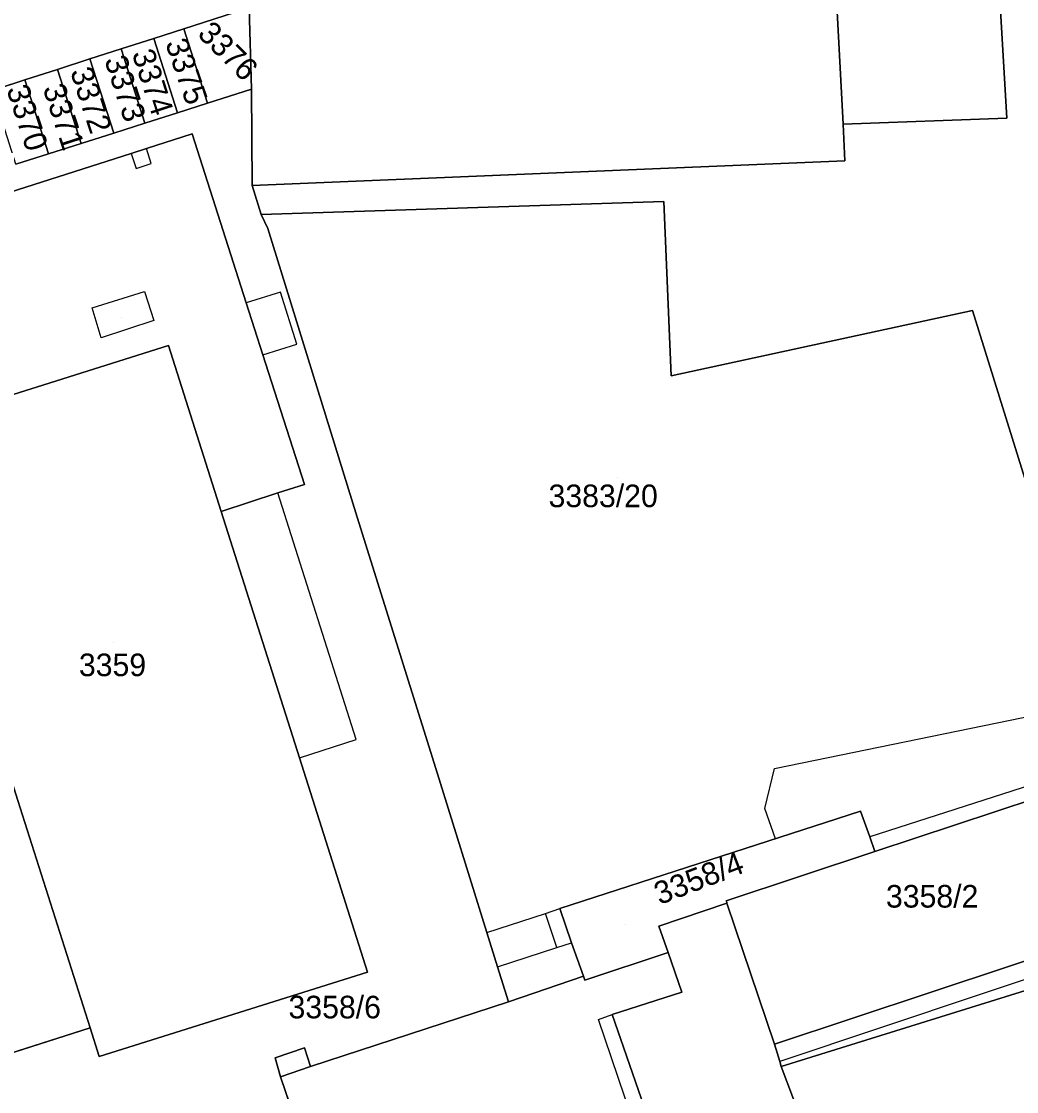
# Model space of a CAD drawing. Extents: x -264070 to -262271, y -1238894 to -1238141.
# Drawn here: x -262811.1 to -262723.1, y -1238591 to -1238496.4 of the extents above; entities that cross this region are included whole.
import ezdxf

# ---------------------------------------------------------------- set-up
doc = ezdxf.new("R2010")
doc.units = 0
for name, color, linetype in [('body_kn', 7, 'Continuous'), ('kladpar_druhypozemkov', 7, 'Continuous'), ('kladpar_hranice', 7, 'Continuous'), ('kladpar_parcelnecisla', 7, 'Continuous'), ('kladpar_plochy', 7, 'Continuous'), ('kladpar_sipky', 7, 'Continuous'), ('tarchy_linie', 7, 'Continuous'), ('zappar_hrandruhpozemk', 7, 'Continuous')]:
    doc.layers.add(name, color=color, linetype=linetype)

msp = doc.modelspace()

# ---------------------------------------------------------------- linework, layer by layer
at = {"layer": 'body_kn'}
for p, q in [((-262796.77, -1238497.02), (-262796.77, -1238497.02)), ((-262796.77, -1238497.02), (-262796.77, -1238497.02)), ((-262799.43, -1238497.87), (-262799.43, -1238497.87)), ((-262799.43, -1238497.87), (-262799.43, -1238497.87)), ((-262802.32, -1238498.8), (-262802.32, -1238498.8)), ((-262802.32, -1238498.8), (-262802.32, -1238498.8)), ((-262805.08, -1238499.69), (-262805.08, -1238499.69)), ((-262805.08, -1238499.69), (-262805.08, -1238499.69)), ((-262807.94, -1238500.61), (-262807.94, -1238500.61)), ((-262807.94, -1238500.61), (-262807.94, -1238500.61)), ((-262810.83, -1238501.54), (-262810.83, -1238501.54)), ((-262810.83, -1238501.54), (-262810.83, -1238501.54)), ((-262790.77, -1238502.37), (-262790.77, -1238502.37)), ((-262794.66, -1238503.61), (-262794.66, -1238503.61)), ((-262797.32, -1238504.45), (-262797.32, -1238504.45)), ((-262723.93, -1238504.93), (-262723.93, -1238504.93)), ((-262800.21, -1238505.37), (-262800.21, -1238505.37)), ((-262738.4, -1238505.46), (-262738.4, -1238505.46)), ((-262802.97, -1238506.25), (-262802.97, -1238506.25)), ((-262796.03, -1238506.32), (-262796.03, -1238506.32)), ((-262805.85, -1238507.16), (-262805.85, -1238507.16)), ((-262800.08, -1238507.61), (-262800.08, -1238507.61)), ((-262808.73, -1238508.07), (-262808.73, -1238508.07)), ((-262801.42, -1238508.04), (-262801.42, -1238508.04)), ((-262801.42, -1238508.04), (-262801.42, -1238508.04)), ((-262738.27, -1238508.71), (-262738.27, -1238508.71)), ((-262800.99, -1238509.37), (-262800.99, -1238509.37)), ((-262799.66, -1238508.95), (-262799.66, -1238508.95)), ((-262790.72, -1238510.89), (-262790.72, -1238510.89)), ((-262754.29, -1238512.3), (-262754.29, -1238512.3)), ((-262789.93, -1238513.46), (-262789.93, -1238513.46)), ((-262789.33, -1238514.68), (-262789.33, -1238514.68)), ((-262789.33, -1238514.68), (-262789.33, -1238514.68)), ((-262800.26, -1238520.25), (-262800.26, -1238520.25)), ((-262788.2, -1238520.31), (-262788.2, -1238520.31)), ((-262804.88, -1238521.71), (-262804.88, -1238521.71)), ((-262804.88, -1238521.71), (-262804.88, -1238521.71)), ((-262791.24, -1238521.26), (-262791.24, -1238521.26)), ((-262726.98, -1238521.95), (-262726.98, -1238521.95)), ((-262799.43, -1238522.84), (-262799.43, -1238522.84)), ((-262804.08, -1238524.35), (-262804.08, -1238524.35)), ((-262786.76, -1238524.92), (-262786.76, -1238524.92)), ((-262798.11, -1238525.04), (-262798.11, -1238525.04)), ((-262789.77, -1238525.86), (-262789.77, -1238525.86)), ((-262789.77, -1238525.86), (-262789.77, -1238525.86)), ((-262753.63, -1238527.72), (-262753.63, -1238527.72)), ((-262786.09, -1238537.33), (-262786.09, -1238537.33)), ((-262788.44, -1238538.08), (-262788.44, -1238538.08)), ((-262793.45, -1238539.72), (-262793.45, -1238539.72)), ((-262781.41, -1238540.21), (-262781.41, -1238540.21)), ((-262781.5, -1238559.9), (-262781.5, -1238559.9)), ((-262786.53, -1238561.5), (-262786.53, -1238561.5)), ((-262786.53, -1238561.5), (-262786.53, -1238561.5)), ((-262774.47, -1238562.46), (-262774.47, -1238562.46)), ((-262744.49, -1238562.45), (-262744.49, -1238562.45)), ((-262745.36, -1238565.99), (-262745.36, -1238565.99)), ((-262736.87, -1238566.23), (-262736.87, -1238566.23)), ((-262736.06, -1238568.51), (-262736.06, -1238568.51)), ((-262744.41, -1238568.67), (-262744.41, -1238568.67)), ((-262735.62, -1238569.81), (-262735.62, -1238569.81)), ((-262735.62, -1238569.81), (-262735.62, -1238569.81)), ((-262748.76, -1238574.16), (-262748.76, -1238574.16)), ((-262763.5, -1238574.85), (-262763.5, -1238574.85)), ((-262748.72, -1238574.29), (-262748.72, -1238574.29)), ((-262748.7, -1238574.36), (-262748.7, -1238574.36)), ((-262748.7, -1238574.36), (-262748.7, -1238574.36)), ((-262764.76, -1238575.28), (-262764.76, -1238575.28)), ((-262764.76, -1238575.28), (-262764.76, -1238575.28)), ((-262769.95, -1238576.95), (-262769.95, -1238576.95)), ((-262769.95, -1238576.95), (-262769.95, -1238576.95)), ((-262754.73, -1238576.41), (-262754.73, -1238576.41)), ((-262762.45, -1238577.87), (-262762.45, -1238577.87)), ((-262763.76, -1238578.28), (-262763.76, -1238578.28)), ((-262763.76, -1238578.28), (-262763.76, -1238578.28)), ((-262753.89, -1238578.72), (-262753.89, -1238578.72)), ((-262780.51, -1238580.47), (-262780.51, -1238580.47)), ((-262769, -1238579.99), (-262769, -1238579.99)), ((-262769, -1238579.99), (-262769, -1238579.99)), ((-262761.4, -1238580.84), (-262761.4, -1238580.84)), ((-262761.27, -1238581.18), (-262761.27, -1238581.18)), ((-262752.69, -1238582.25), (-262752.69, -1238582.25)), ((-262768.04, -1238583.09), (-262768.04, -1238583.09)), ((-262760.08, -1238584.65), (-262760.08, -1238584.65)), ((-262758.86, -1238584.22), (-262758.86, -1238584.22)), ((-262805.06, -1238585.39), (-262805.06, -1238585.39)), ((-262805.06, -1238585.39), (-262805.06, -1238585.39)), ((-262786.09, -1238587.16), (-262786.09, -1238587.16)), ((-262786.09, -1238587.16), (-262786.09, -1238587.16)), ((-262744.5, -1238586.83), (-262744.5, -1238586.83)), ((-262804.25, -1238587.93), (-262804.25, -1238587.93)), ((-262788.67, -1238588.04), (-262788.67, -1238588.04)), ((-262744.02, -1238588.38), (-262744.02, -1238588.38)), ((-262785.54, -1238588.81), (-262785.54, -1238588.81)), ((-262743.89, -1238588.82), (-262743.89, -1238588.82)), ((-262788.2, -1238589.74), (-262788.2, -1238589.74))]:
    msp.add_line(p, q, dxfattribs=at)
at = {"layer": 'kladpar_druhypozemkov'}
for p, q in [((-262793.4, -1238496.86), (-262793.4, -1238496.86)), ((-262798.8, -1238501.35), (-262798.8, -1238501.35)), ((-262796.18, -1238500.62), (-262796.18, -1238500.62)), ((-262801.67, -1238502.05), (-262801.67, -1238502.05)), ((-262804.45, -1238502.96), (-262804.45, -1238502.96)), ((-262807.32, -1238503.67), (-262807.32, -1238503.67)), ((-262810.46, -1238504.27), (-262810.46, -1238504.27)), ((-262800.62, -1238508.83), (-262800.62, -1238508.83)), ((-262802.3, -1238522.6), (-262802.3, -1238522.6)), ((-262758.37, -1238536.74), (-262758.37, -1238536.74)), ((-262802.96, -1238551.34), (-262802.96, -1238551.34)), ((-262729.5, -1238572.66), (-262729.5, -1238572.66)), ((-262757.65, -1238576.25), (-262757.65, -1238576.25)), ((-262787.57, -1238589.32), (-262787.57, -1238589.32))]:
    msp.add_line(p, q, dxfattribs=at)
at = {"layer": 'kladpar_hranice'}
msp.add_line((-262805.06, -1238585.39), (-262815.78, -1238588.82), dxfattribs=at)
for points in [[(-262739.57, -1238484.61), (-262739.45, -1238486.09), (-262738.4, -1238505.46), (-262738.27, -1238508.71), (-262790.72, -1238510.89), (-262790.77, -1238502.37), (-262790.97, -1238495.17), (-262791.38, -1238486.73), (-262739.57, -1238484.61)], [(-262724.99, -1238486.89), (-262723.93, -1238504.93), (-262738.4, -1238505.46), (-262739.45, -1238486.09), (-262737.11, -1238486.08), (-262737.05, -1238487.48), (-262724.99, -1238486.89)], [(-262716.29, -1238486.45), (-262699.75, -1238554.24), (-262695.25, -1238572.71), (-262698.48, -1238574.68), (-262701.48, -1238573.5), (-262703.47, -1238572.14), (-262704.97, -1238570.14), (-262705.65, -1238568.75), (-262707.39, -1238563.2), (-262712.33, -1238564.89), (-262713.33, -1238565.23), (-262714.19, -1238562.73), (-262714.62, -1238561.6), (-262726.98, -1238521.95), (-262753.63, -1238527.72), (-262754.29, -1238512.3), (-262789.93, -1238513.46), (-262790.72, -1238510.89), (-262738.27, -1238508.71), (-262738.4, -1238505.46), (-262723.93, -1238504.93), (-262724.99, -1238486.89), (-262724.95, -1238486.89)], [(-262792.28, -1238495.59), (-262796.77, -1238497.02), (-262799.43, -1238497.87), (-262802.32, -1238498.8), (-262805.08, -1238499.69), (-262807.94, -1238500.61), (-262810.83, -1238501.54), (-262813.73, -1238502.47)], [(-262792.28, -1238495.59), (-262790.97, -1238495.17), (-262790.77, -1238502.37), (-262794.66, -1238503.61), (-262796.77, -1238497.02), (-262792.28, -1238495.59)], [(-262796.77, -1238497.02), (-262794.66, -1238503.61), (-262797.32, -1238504.45), (-262799.43, -1238497.87), (-262796.77, -1238497.02)], [(-262799.43, -1238497.87), (-262797.32, -1238504.45), (-262800.21, -1238505.37), (-262802.32, -1238498.8), (-262799.43, -1238497.87)], [(-262802.32, -1238498.8), (-262800.21, -1238505.37), (-262802.97, -1238506.25), (-262805.08, -1238499.69), (-262802.32, -1238498.8)], [(-262805.08, -1238499.69), (-262802.97, -1238506.25), (-262805.85, -1238507.16), (-262807.94, -1238500.61), (-262805.08, -1238499.69)], [(-262807.94, -1238500.61), (-262805.85, -1238507.16), (-262808.73, -1238508.07), (-262810.83, -1238501.54), (-262807.94, -1238500.61)], [(-262810.83, -1238501.54), (-262808.73, -1238508.07), (-262811.63, -1238509), (-262813.73, -1238502.47), (-262810.83, -1238501.54)], [(-262811.63, -1238509), (-262808.73, -1238508.07), (-262805.85, -1238507.16), (-262802.97, -1238506.25), (-262800.21, -1238505.37), (-262797.32, -1238504.45), (-262794.66, -1238503.61), (-262790.77, -1238502.37), (-262790.72, -1238510.89), (-262789.93, -1238513.46), (-262789.33, -1238514.68)], [(-262849.6, -1238529), (-262851.22, -1238523.96), (-262847.32, -1238522.71), (-262801.42, -1238508.04), (-262800.08, -1238507.61), (-262796.03, -1238506.32), (-262791.24, -1238521.26), (-262789.77, -1238525.86), (-262786.09, -1238537.33), (-262788.44, -1238538.08), (-262793.45, -1238539.72), (-262798.11, -1238525.04), (-262821.89, -1238532.52), (-262814.67, -1238555.2), (-262811.45, -1238565.3), (-262805.06, -1238585.39)], [(-262793.45, -1238539.72), (-262788.44, -1238538.08), (-262786.09, -1238537.33), (-262789.77, -1238525.86), (-262791.24, -1238521.26), (-262796.03, -1238506.32), (-262800.08, -1238507.61), (-262801.42, -1238508.04), (-262847.32, -1238522.71), (-262851.22, -1238523.96), (-262849.6, -1238529)], [(-262789.33, -1238514.68), (-262789.93, -1238513.46), (-262754.29, -1238512.3), (-262753.63, -1238527.72), (-262726.98, -1238521.95), (-262714.62, -1238561.6), (-262714.19, -1238562.73), (-262735.62, -1238569.81), (-262736.06, -1238568.51), (-262736.87, -1238566.23), (-262763.5, -1238574.85), (-262762.45, -1238577.87), (-262761.4, -1238580.84), (-262768.04, -1238583.09), (-262769, -1238579.99), (-262769.95, -1238576.95), (-262774.47, -1238562.46), (-262781.41, -1238540.21), (-262789.33, -1238514.68)], [(-262789.33, -1238514.68), (-262781.41, -1238540.21), (-262774.47, -1238562.46), (-262769.95, -1238576.95), (-262769, -1238579.99), (-262768.04, -1238583.09), (-262785.54, -1238588.81), (-262786.09, -1238587.16), (-262788.67, -1238588.04), (-262788.2, -1238589.74), (-262783.26, -1238604.28), (-262795.11, -1238608.29), (-262796.01, -1238608.64), (-262798.03, -1238609.31), (-262798.63, -1238609.46), (-262801.88, -1238630.97), (-262802.35, -1238634.79), (-262813.39, -1238638.51)], [(-262821.89, -1238532.52), (-262798.11, -1238525.04), (-262793.45, -1238539.72), (-262786.53, -1238561.5), (-262780.51, -1238580.47), (-262804.25, -1238587.93), (-262805.06, -1238585.39), (-262811.45, -1238565.3), (-262814.67, -1238555.2), (-262821.89, -1238532.52)], [(-262815.78, -1238588.82), (-262805.06, -1238585.39), (-262804.25, -1238587.93), (-262780.51, -1238580.47), (-262786.53, -1238561.5), (-262793.45, -1238539.72)], [(-262714.19, -1238562.73), (-262713.33, -1238565.23), (-262709.83, -1238575.35), (-262744.5, -1238586.83), (-262748.7, -1238574.36), (-262748.72, -1238574.29), (-262748.76, -1238574.16), (-262735.62, -1238569.81), (-262714.19, -1238562.73)], [(-262707.39, -1238563.2), (-262705.65, -1238568.75), (-262704.97, -1238570.14), (-262703.47, -1238572.14), (-262701.48, -1238573.5), (-262698.48, -1238574.68), (-262743.89, -1238588.82), (-262744.02, -1238588.38), (-262744.5, -1238586.83), (-262709.83, -1238575.35), (-262713.33, -1238565.23), (-262712.33, -1238564.89), (-262707.39, -1238563.2)], [(-262735.62, -1238569.81), (-262748.76, -1238574.16), (-262748.72, -1238574.29), (-262748.7, -1238574.36), (-262754.73, -1238576.41), (-262753.89, -1238578.72), (-262761.27, -1238581.18), (-262761.4, -1238580.84), (-262762.45, -1238577.87), (-262763.5, -1238574.85), (-262736.87, -1238566.23), (-262736.06, -1238568.51), (-262735.62, -1238569.81)], [(-262748.7, -1238574.36), (-262744.5, -1238586.83), (-262744.02, -1238588.38), (-262743.89, -1238588.82), (-262742.82, -1238591.72), (-262741.51, -1238595.33), (-262739.88, -1238599.8), (-262743.79, -1238601.11), (-262744.26, -1238599.95), (-262749.26, -1238601.54), (-262751.19, -1238602.22), (-262753.15, -1238600.87), (-262753.73, -1238599.01), (-262758.86, -1238584.22), (-262752.69, -1238582.25), (-262753.89, -1238578.72), (-262754.73, -1238576.41), (-262748.7, -1238574.36)], [(-262716.97, -1238612.82), (-262723.53, -1238614.84), (-262724.33, -1238612.29), (-262725.39, -1238608.86), (-262729.39, -1238596.03), (-262731.24, -1238594.86), (-262733.44, -1238593.97), (-262736.1, -1238593.48), (-262741.51, -1238595.33), (-262742.82, -1238591.72), (-262743.89, -1238588.82), (-262698.48, -1238574.68)], [(-262775.73, -1238625.98), (-262780.15, -1238613.32), (-262783.26, -1238604.28), (-262788.2, -1238589.74), (-262785.54, -1238588.81), (-262768.04, -1238583.09), (-262761.4, -1238580.84), (-262761.27, -1238581.18), (-262753.89, -1238578.72), (-262752.69, -1238582.25), (-262758.86, -1238584.22), (-262753.73, -1238599.01), (-262753.15, -1238600.87), (-262751.19, -1238602.22), (-262749.26, -1238601.54), (-262744.26, -1238599.95), (-262743.79, -1238601.11), (-262739.88, -1238599.8), (-262739.82, -1238599.96), (-262735.54, -1238612.51), (-262771.01, -1238624.31), (-262775.73, -1238625.98)], [(-262786.09, -1238587.16), (-262785.54, -1238588.81), (-262788.2, -1238589.74), (-262788.67, -1238588.04), (-262786.09, -1238587.16)]]:
    msp.add_lwpolyline(points, dxfattribs=at)
at = {"layer": 'kladpar_plochy'}
for p, q in [((-262723.93, -1238504.93), (-262724.99, -1238486.89)), ((-262792.28, -1238495.59), (-262796.77, -1238497.02)), ((-262796.77, -1238497.02), (-262799.43, -1238497.87)), ((-262799.43, -1238497.87), (-262802.32, -1238498.8)), ((-262802.32, -1238498.8), (-262805.08, -1238499.69)), ((-262805.08, -1238499.69), (-262807.94, -1238500.61)), ((-262807.94, -1238500.61), (-262810.83, -1238501.54)), ((-262810.83, -1238501.54), (-262813.73, -1238502.47)), ((-262794.66, -1238503.61), (-262790.77, -1238502.37)), ((-262790.77, -1238502.37), (-262790.72, -1238510.89)), ((-262797.32, -1238504.45), (-262794.66, -1238503.61)), ((-262800.21, -1238505.37), (-262797.32, -1238504.45)), ((-262738.4, -1238505.46), (-262723.93, -1238504.93)), ((-262802.97, -1238506.25), (-262800.21, -1238505.37)), ((-262738.27, -1238508.71), (-262738.4, -1238505.46)), ((-262805.85, -1238507.16), (-262802.97, -1238506.25)), ((-262796.03, -1238506.32), (-262800.08, -1238507.61)), ((-262791.24, -1238521.26), (-262796.03, -1238506.32)), ((-262808.73, -1238508.07), (-262805.85, -1238507.16)), ((-262800.08, -1238507.61), (-262801.42, -1238508.04)), ((-262801.42, -1238508.04), (-262847.32, -1238522.71)), ((-262811.63, -1238509), (-262808.73, -1238508.07)), ((-262790.72, -1238510.89), (-262738.27, -1238508.71)), ((-262789.93, -1238513.46), (-262790.72, -1238510.89)), ((-262790.72, -1238510.89), (-262789.93, -1238513.46)), ((-262754.29, -1238512.3), (-262789.93, -1238513.46)), ((-262753.63, -1238527.72), (-262754.29, -1238512.3)), ((-262789.93, -1238513.46), (-262789.33, -1238514.68)), ((-262789.33, -1238514.68), (-262781.41, -1238540.21)), ((-262789.77, -1238525.86), (-262791.24, -1238521.26)), ((-262726.98, -1238521.95), (-262753.63, -1238527.72)), ((-262714.62, -1238561.6), (-262726.98, -1238521.95)), ((-262786.09, -1238537.33), (-262789.77, -1238525.86)), ((-262788.44, -1238538.08), (-262786.09, -1238537.33)), ((-262793.45, -1238539.72), (-262788.44, -1238538.08)), ((-262786.53, -1238561.5), (-262793.45, -1238539.72)), ((-262781.41, -1238540.21), (-262774.47, -1238562.46)), ((-262780.51, -1238580.47), (-262786.53, -1238561.5)), ((-262774.47, -1238562.46), (-262769.95, -1238576.95)), ((-262769.95, -1238576.95), (-262769, -1238579.99)), ((-262804.25, -1238587.93), (-262780.51, -1238580.47)), ((-262769, -1238579.99), (-262768.04, -1238583.09)), ((-262768.04, -1238583.09), (-262785.54, -1238588.81)), ((-262815.78, -1238588.82), (-262805.06, -1238585.39)), ((-262805.06, -1238585.39), (-262804.25, -1238587.93)), ((-262786.09, -1238587.16), (-262788.67, -1238588.04)), ((-262785.54, -1238588.81), (-262786.09, -1238587.16)), ((-262788.67, -1238588.04), (-262788.2, -1238589.74)), ((-262788.2, -1238589.74), (-262783.26, -1238604.28))]:
    msp.add_line(p, q, dxfattribs=at)
for points in [[(-262739.57, -1238484.61), (-262739.45, -1238486.09), (-262738.4, -1238505.46), (-262738.27, -1238508.71), (-262790.72, -1238510.89), (-262790.77, -1238502.37), (-262790.97, -1238495.17), (-262791.38, -1238486.73)], [(-262724.99, -1238486.89), (-262723.93, -1238504.93), (-262738.4, -1238505.46), (-262739.45, -1238486.09), (-262737.11, -1238486.08), (-262737.05, -1238487.48)], [(-262792.28, -1238495.59), (-262790.97, -1238495.17), (-262790.77, -1238502.37), (-262794.66, -1238503.61), (-262796.77, -1238497.02)], [(-262796.77, -1238497.02), (-262794.66, -1238503.61), (-262797.32, -1238504.45), (-262799.43, -1238497.87)], [(-262799.43, -1238497.87), (-262797.32, -1238504.45), (-262800.21, -1238505.37), (-262802.32, -1238498.8)], [(-262802.32, -1238498.8), (-262800.21, -1238505.37), (-262802.97, -1238506.25), (-262805.08, -1238499.69)], [(-262805.08, -1238499.69), (-262802.97, -1238506.25), (-262805.85, -1238507.16), (-262807.94, -1238500.61)], [(-262807.94, -1238500.61), (-262805.85, -1238507.16), (-262808.73, -1238508.07), (-262810.83, -1238501.54)], [(-262810.83, -1238501.54), (-262808.73, -1238508.07), (-262811.63, -1238509), (-262813.73, -1238502.47)], [(-262805.06, -1238585.39), (-262815.78, -1238588.82), (-262822.62, -1238591), (-262827.26, -1238576.59), (-262829.18, -1238570.6), (-262830.35, -1238566.96), (-262841.08, -1238533.44), (-262847.5, -1238535.5), (-262847.79, -1238534.6), (-262849.6, -1238529), (-262851.22, -1238523.96), (-262847.32, -1238522.71), (-262801.42, -1238508.04), (-262800.08, -1238507.61), (-262796.03, -1238506.32), (-262791.24, -1238521.26), (-262789.77, -1238525.86), (-262786.09, -1238537.33), (-262788.44, -1238538.08), (-262793.45, -1238539.72), (-262798.11, -1238525.04), (-262821.89, -1238532.52), (-262814.67, -1238555.2), (-262811.45, -1238565.3)], [(-262789.33, -1238514.68), (-262789.93, -1238513.46), (-262754.29, -1238512.3), (-262753.63, -1238527.72), (-262726.98, -1238521.95), (-262714.62, -1238561.6), (-262714.19, -1238562.73), (-262735.62, -1238569.81), (-262736.06, -1238568.51), (-262736.87, -1238566.23), (-262763.5, -1238574.85), (-262762.45, -1238577.87), (-262761.4, -1238580.84), (-262768.04, -1238583.09), (-262769, -1238579.99), (-262769.95, -1238576.95), (-262774.47, -1238562.46), (-262781.41, -1238540.21)], [(-262821.89, -1238532.52), (-262798.11, -1238525.04), (-262793.45, -1238539.72), (-262786.53, -1238561.5), (-262780.51, -1238580.47), (-262804.25, -1238587.93), (-262805.06, -1238585.39), (-262811.45, -1238565.3), (-262814.67, -1238555.2)], [(-262714.19, -1238562.73), (-262713.33, -1238565.23), (-262709.83, -1238575.35), (-262744.5, -1238586.83), (-262748.7, -1238574.36), (-262748.72, -1238574.29), (-262748.76, -1238574.16), (-262735.62, -1238569.81)], [(-262707.39, -1238563.2), (-262705.65, -1238568.75), (-262704.97, -1238570.14), (-262703.47, -1238572.14), (-262701.48, -1238573.5), (-262698.48, -1238574.68), (-262743.89, -1238588.82), (-262744.02, -1238588.38), (-262744.5, -1238586.83), (-262709.83, -1238575.35), (-262713.33, -1238565.23), (-262712.33, -1238564.89)], [(-262735.62, -1238569.81), (-262748.76, -1238574.16), (-262748.72, -1238574.29), (-262748.7, -1238574.36), (-262754.73, -1238576.41), (-262753.89, -1238578.72), (-262761.27, -1238581.18), (-262761.4, -1238580.84), (-262762.45, -1238577.87), (-262763.5, -1238574.85), (-262736.87, -1238566.23), (-262736.06, -1238568.51)], [(-262748.7, -1238574.36), (-262744.5, -1238586.83), (-262744.02, -1238588.38), (-262743.89, -1238588.82), (-262742.82, -1238591.72), (-262741.51, -1238595.33), (-262739.88, -1238599.8), (-262743.79, -1238601.11), (-262744.26, -1238599.95), (-262749.26, -1238601.54), (-262751.19, -1238602.22), (-262753.15, -1238600.87), (-262753.73, -1238599.01), (-262758.86, -1238584.22), (-262752.69, -1238582.25), (-262753.89, -1238578.72), (-262754.73, -1238576.41)], [(-262775.73, -1238625.98), (-262780.15, -1238613.32), (-262783.26, -1238604.28), (-262788.2, -1238589.74), (-262785.54, -1238588.81), (-262768.04, -1238583.09), (-262761.4, -1238580.84), (-262761.27, -1238581.18), (-262753.89, -1238578.72), (-262752.69, -1238582.25), (-262758.86, -1238584.22), (-262753.73, -1238599.01), (-262753.15, -1238600.87), (-262751.19, -1238602.22), (-262749.26, -1238601.54), (-262744.26, -1238599.95), (-262743.79, -1238601.11), (-262739.88, -1238599.8), (-262739.82, -1238599.96), (-262735.54, -1238612.51), (-262771.01, -1238624.31)], [(-262786.09, -1238587.16), (-262785.54, -1238588.81), (-262788.2, -1238589.74), (-262788.67, -1238588.04)]]:
    msp.add_lwpolyline(points, close=True, dxfattribs=at)
msp.add_lwpolyline([(-262716.97, -1238612.82), (-262723.53, -1238614.84), (-262724.33, -1238612.29), (-262725.39, -1238608.86), (-262729.39, -1238596.03), (-262731.24, -1238594.86), (-262733.44, -1238593.97), (-262736.1, -1238593.48), (-262741.51, -1238595.33), (-262742.82, -1238591.72), (-262743.89, -1238588.82), (-262698.48, -1238574.68)], dxfattribs=at)
at = {"layer": 'kladpar_sipky'}
msp.add_line((-262786.22, -1238588.56), (-262786.22, -1238588.56), dxfattribs=at)
at = {"layer": 'tarchy_linie'}
msp.add_lwpolyline([(-262744.41, -1238568.67), (-262745.36, -1238565.99), (-262744.49, -1238562.45), (-262719.02, -1238557.24), (-262718.03, -1238559.85), (-262715.45, -1238558.95)], dxfattribs=at)
at = {"layer": 'zappar_hrandruhpozemk'}
for p, q in [((-262799.66, -1238508.95), (-262800.08, -1238507.61)), ((-262801.42, -1238508.04), (-262800.99, -1238509.37)), ((-262800.99, -1238509.37), (-262799.66, -1238508.95)), ((-262804.88, -1238521.71), (-262800.26, -1238520.25)), ((-262788.2, -1238520.31), (-262791.24, -1238521.26)), ((-262786.76, -1238524.92), (-262788.2, -1238520.31)), ((-262789.77, -1238525.86), (-262786.76, -1238524.92)), ((-262781.5, -1238559.9), (-262788.44, -1238538.08)), ((-262786.53, -1238561.5), (-262781.5, -1238559.9)), ((-262714.62, -1238561.6), (-262736.06, -1238568.51)), ((-262764.76, -1238575.28), (-262763.5, -1238574.85)), ((-262769.95, -1238576.95), (-262764.76, -1238575.28)), ((-262763.76, -1238578.28), (-262764.76, -1238575.28)), ((-262760.08, -1238584.65), (-262758.86, -1238584.22)), ((-262753.36, -1238604.31), (-262760.08, -1238584.65))]:
    msp.add_line(p, q, dxfattribs=at)
for points in [[(-262800.26, -1238520.25), (-262799.43, -1238522.84), (-262804.08, -1238524.35), (-262804.88, -1238521.71)], [(-262712.33, -1238564.89), (-262708.37, -1238576.46), (-262744.02, -1238588.38)], [(-262769, -1238579.99), (-262763.76, -1238578.28), (-262762.45, -1238577.87)]]:
    msp.add_lwpolyline(points, dxfattribs=at)

# ---------------------------------------------------------------- texts
at = {"layer": 'kladpar_parcelnecisla'}
for s, rotation, p in [('3376', 315, (-262795.648, -1238497.577)), ('3375', 289, (-262798.427, -1238498.284)), ('3373', 288, (-262803.812, -1238499.764)), ('3374', 288, (-262801.381, -1238499.201)), ('3372', 288, (-262806.838, -1238500.789)), ('3370', 288, (-262812.48, -1238502.352)), ('3371', 288, (-262809.264, -1238502.271)), ('3358/4', 21, (-262754.662, -1238574.546))]:
    msp.add_text(s, height=2, rotation=rotation, dxfattribs=at).set_placement(p)
for s, p in [('3383/20', (-262764.488, -1238539.34)), ('3359', (-262806.05, -1238554.29)), ('3358/2', (-262734.628, -1238574.76)), ('3358/6', (-262787.501, -1238584.56))]:
    msp.add_text(s, height=2, dxfattribs=at).set_placement(p)

doc.saveas('drawing.dxf')
